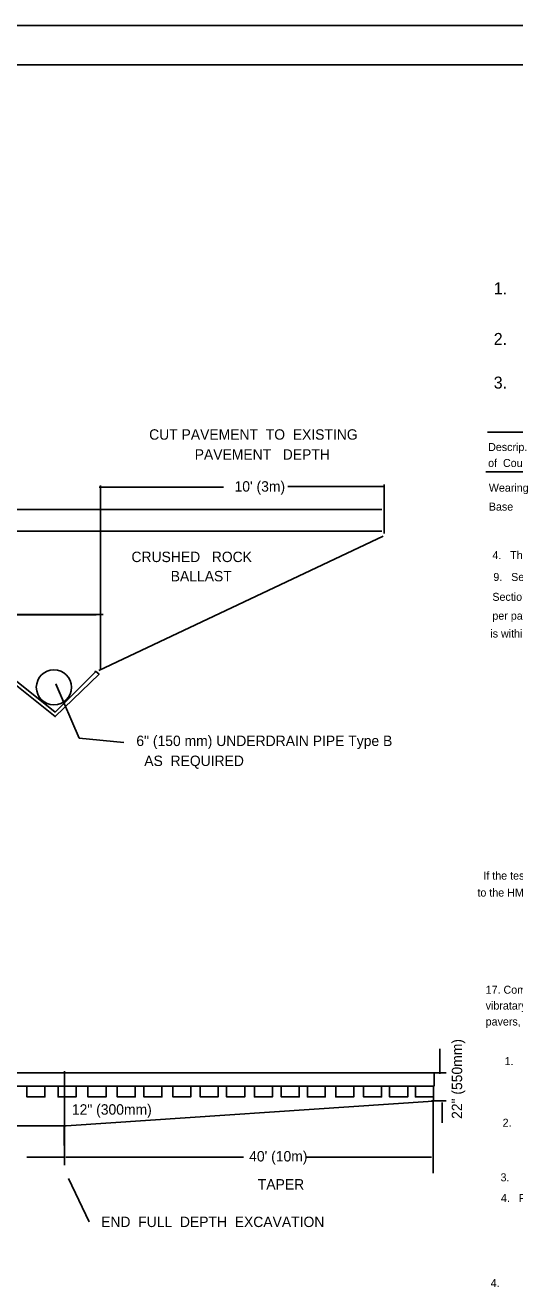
# Model space of a CAD drawing. Extents: x 1100953.69 to 1100956.55, y 386728.28 to 386730.11.
# Drawn here: x 1100955.371 to 1100955.772, y 386729.072 to 386730.11 of the extents above; entities that cross this region are included whole.
import ezdxf

# ---------------------------------------------------------------- set-up
doc = ezdxf.new("R2010")
doc.units = 0
for name, color, linetype in [('BORDER', 7, 'Continuous'), ('Level 1', 7, 'Continuous'), ('Level 33', 7, 'Continuous'), ('ORIG TOPO TEXT', 7, 'Continuous'), ('PLOT BOUNDARY', 7, 'Continuous'), ('ROADWAY TEXT', 7, 'Continuous')]:
    doc.layers.add(name, color=color, linetype=linetype)

msp = doc.modelspace()

# ---------------------------------------------------------------- linework, layer by layer
at = {"layer": 'BORDER'}
msp.add_line((1100956.4931, 386730.0776), (1100953.8264, 386730.0776), dxfattribs=at)
at = {"layer": 'Level 1'}
for p, q in [((1100955.4725, 386729.731), (1100955.5332, 386729.731)), ((1100955.6383, 386729.7317), (1100955.5861, 386729.7317)), ((1100955.4308, 386729.5806), (1100955.6643, 386729.6908)), ((1100953.8943, 386729.2506), (1100955.7055, 386729.2506)), ((1100955.7062, 386729.2506), (1100955.7062, 386729.2398)), ((1100955.4028, 386729.2451), (1100955.4028, 386729.175)), ((1100955.7052, 386729.2398), (1100955.7061, 386729.2398)), ((1100955.7053, 386729.2279), (1100955.7053, 386729.1684)), ((1100955.7055, 386729.2308), (1100955.7055, 386729.2275)), ((1100955.5496, 386729.1813), (1100955.4038, 386729.1813)), ((1100955.6008, 386729.1813), (1100955.704, 386729.1813))]:
    msp.add_line(p, q, dxfattribs=at)
for points in [[(1100955.4278, 386729.5793), (1100955.395, 386729.5465), (1100955.3578, 386729.5763), (1100955.3578, 386729.5763), (1100954.7625, 386729.591), (1100954.1599, 386729.574), (1100954.1361, 386729.5502), (1100954.1075, 386729.5787)], [(1100954.1044, 386729.5735), (1100954.1351, 386729.5442), (1100954.1598, 386729.5701), (1100954.7626, 386729.5873), (1100955.3554, 386729.5746), (1100955.3951, 386729.5429), (1100955.4313, 386729.5776), (1100955.4313, 386729.5776), (1100955.4313, 386729.5776), (1100955.4313, 386729.5776)], [(1100955.7055, 386729.2398), (1100953.8939, 386729.2398), (1100953.8939, 386729.2503)], [(1100953.8943, 386729.2398), (1100953.8943, 386729.2506), (1100953.8943, 386729.2506), (1100955.7062, 386729.2506), (1100955.7062, 386729.2398)], [(1100953.8943, 386729.2398), (1100953.8943, 386729.2398), (1100955.7055, 386729.2398)], [(1100955.3719, 386729.2398), (1100955.3719, 386729.2308), (1100955.3866, 386729.2308), (1100955.3866, 386729.2398)], [(1100955.3974, 386729.2398), (1100955.3974, 386729.2308), (1100955.4122, 386729.2308), (1100955.4122, 386729.2398)], [(1100955.422, 386729.2398), (1100955.422, 386729.2308), (1100955.4368, 386729.2308), (1100955.4368, 386729.2398)], [(1100955.446, 386729.2398), (1100955.446, 386729.2308), (1100955.4608, 386729.2308), (1100955.4608, 386729.2398)], [(1100955.4679, 386729.2398), (1100955.4679, 386729.2308), (1100955.4827, 386729.2308), (1100955.4827, 386729.2398)], [(1100955.4917, 386729.2398), (1100955.4917, 386729.2308), (1100955.5064, 386729.2308), (1100955.5064, 386729.2398)], [(1100955.5141, 386729.2398), (1100955.5141, 386729.2308), (1100955.5288, 386729.2308), (1100955.5288, 386729.2398)], [(1100955.5358, 386729.2398), (1100955.5358, 386729.2308), (1100955.5506, 386729.2308), (1100955.5506, 386729.2398)], [(1100955.5586, 386729.2398), (1100955.5586, 386729.2308), (1100955.5734, 386729.2308), (1100955.5734, 386729.2398)], [(1100955.5806, 386729.2398), (1100955.5806, 386729.2308), (1100955.5954, 386729.2308), (1100955.5954, 386729.2398)], [(1100955.6021, 386729.2398), (1100955.6021, 386729.2308), (1100955.6168, 386729.2308), (1100955.6168, 386729.2398)], [(1100955.6253, 386729.2398), (1100955.6253, 386729.2308), (1100955.6401, 386729.2308), (1100955.6401, 386729.2398)], [(1100955.6482, 386729.2398), (1100955.6482, 386729.2308), (1100955.6629, 386729.2308), (1100955.6629, 386729.2398)], [(1100955.6696, 386729.2398), (1100955.6696, 386729.2308), (1100955.6844, 386729.2308), (1100955.6844, 386729.2398)], [(1100955.6907, 386729.2398), (1100955.6907, 386729.2308), (1100955.7055, 386729.2308), (1100955.7055, 386729.2398)], [(1100954.1987, 386729.2072), (1100955.4041, 386729.2072), (1100955.7053, 386729.2275)]]:
    msp.add_lwpolyline(points, dxfattribs=at)
msp.add_circle((1100955.394, 386729.5669), 0.0144, dxfattribs=at)
at = {"layer": 'Level 33'}
for p, q in [((1100955.4323, 386729.7324), (1100955.4323, 386729.5818)), ((1100955.6651, 386729.7333), (1100955.6651, 386729.6931)), ((1100954.906, 386729.7126), (1100955.6632, 386729.7126)), ((1100955.6632, 386729.6949), (1100955.0388, 386729.6949)), ((1100954.8967, 386729.6263), (1100955.4288, 386729.6263)), ((1100954.9025, 386729.6266), (1100955.4346, 386729.6266))]:
    msp.add_line(p, q, dxfattribs=at)
msp.add_lwpolyline([(1100955.3958, 386729.569), (1100955.4149, 386729.5252), (1100955.4514, 386729.5215)], dxfattribs=at)
at = {"layer": 'ORIG TOPO TEXT'}
for p, q in [((1100955.7499, 386729.7762), (1100956.2809, 386729.7762)), ((1100955.7485, 386729.7436), (1100956.2795, 386729.7436)), ((1100955.4725, 386729.731), (1100955.4311, 386729.731)), ((1100955.6383, 386729.7317), (1100955.6648, 386729.7317)), ((1100955.4167, 386729.6267), (1100955.4301, 386729.6267)), ((1100955.4021, 386729.5545), (1100955.3957, 386729.5698)), ((1100955.7109, 386729.2704), (1100955.7109, 386729.2497)), ((1100955.4027, 386729.2519), (1100955.4027, 386729.2312)), ((1100955.7039, 386729.2507), (1100955.7159, 386729.2507)), ((1100955.7039, 386729.2276), (1100955.7159, 386729.2276)), ((1100955.7126, 386729.2096), (1100955.7126, 386729.2263)), ((1100955.4025, 386729.1909), (1100955.4025, 386729.2076)), ((1100955.3719, 386729.1814), (1100955.4019, 386729.1814)), ((1100955.423, 386729.1283), (1100955.4059, 386729.164))]:
    msp.add_line(p, q, dxfattribs=at)
msp.add_lwpolyline([(1100955.4313, 386729.5776), (1100955.4283, 386729.58), (1100955.4278, 386729.5793)], dxfattribs=at)
at = {"layer": 'PLOT BOUNDARY'}
msp.add_lwpolyline([(1100953.6916, 386728.2766), (1100956.5249, 386728.2766), (1100956.5249, 386730.1099), (1100953.6916, 386730.1099)], close=True, dxfattribs=at)

# ---------------------------------------------------------------- texts
at = {"layer": 'ORIG TOPO TEXT'}
for s, height, p in [('1.', 0.00984, (1100955.755, 386729.8892)), ('2.', 0.00984, (1100955.755, 386729.8477)), ('3.', 0.00984, (1100955.755, 386729.8119)), ('CUT PAVEMENT  TO  EXISTING', 0.008531, (1100955.4722, 386729.77)), ('Descrip.', 0.00656, (1100955.7504, 386729.7607)), ('PAVEMENT   DEPTH', 0.008531, (1100955.5096, 386729.7536)), ('of  Course', 0.00656, (1100955.7504, 386729.7476)), ("10' (3m)", 0.00853, (1100955.5423, 386729.7274)), ('Wearing', 0.00656, (1100955.751, 386729.7273)), ('Base', 0.00656, (1100955.751, 386729.7118)), ('CRUSHED   ROCK', 0.008531, (1100955.4577, 386729.6696)), ('CRUSHED   ROCK', 0.008531, (1100955.4577, 386729.6696)), ('4.   The design traffic level for the mix placed shall  be 0.3 to <3million ESALS', 0.006563, (1100955.7539, 386729.672)), ('BALLAST', 0.00853, (1100955.4899, 386729.6538)), ('9.   Section 106.6 Acceptance,(2) Method C-For hot mix asphalt designated as Method C in Special Provision ', 0.006563, (1100955.7547, 386729.6541)), ('Section 403 -Hot Mix Asphalt, one sample will be taken from the paver hopper or the truck body per 250 ton', 0.006563, (1100955.7539, 386729.6378)), ('per pay item. The mix will be tested for gradation and PGAB content. Disputes will not be allowed.  If the mix', 0.006563, (1100955.7539, 386729.6223)), ('is within tolerances listed in Table 9, Method C the Department will pay the contract unit price.', 0.006563, (1100955.7522, 386729.6077)), ('6" (150 mm) UNDERDRAIN PIPE Type B', 0.008531, (1100955.4617, 386729.5187)), ('AS  REQUIRED', 0.008531, (1100955.4682, 386729.5023)), ('If the test results for each 250 ton increment are outside these limits the following deductions(Table 9b) shall apply', 0.006563, (1100955.7465, 386729.4091)), (' to the HMA quantity represented by the test. A second consecutive failing test shall result in cessation of production', 0.006563, (1100955.7392, 386729.3952)), ('17. Compaction of the new Hot Mix Asphalt Pavement will be obtained using a minimal roller train consisting of a 3-5 ton', 0.006563, (1100955.7484, 386729.3155)), ('vibratary roller. An approved release agent is required to ensure the mixture does not adhere to hand tools,rollers, ', 0.006563, (1100955.7484, 386729.3025)), ('pavers, and truck bodies. The use of petroleum based fuel oils will not be permitted', 0.006563, (1100955.7484, 386729.2894)), ('1.   ', 0.00656, (1100955.7639, 386729.2569)), ('12" (300mm)', 0.008531, (1100955.4088, 386729.2163)), ('2.   ', 0.00656, (1100955.7623, 386729.2064)), ("40' (10m)", 0.00853, (1100955.5543, 386729.1779)), ('3.', 0.00656, (1100955.7606, 386729.1616)), ('TAPER', 0.00853, (1100955.5614, 386729.1549)), ('4.   Paved shoulders within the gage of the rail to point 24" (650mm) outside of the field side of each rail', 0.006563, (1100955.7609, 386729.1446)), ('END  FULL  DEPTH  EXCAVATION', 0.008531, (1100955.4328, 386729.1241))]:
    msp.add_text(s, height=height, dxfattribs=at).set_placement(p)
msp.add_text('22" (550mm)', height=0.008531, rotation=90, dxfattribs=at).set_placement((1100955.7291, 386729.2128))
at = {"layer": 'ROADWAY TEXT'}
msp.add_text('4.', height=0.00656, dxfattribs=at).set_placement((1100955.7525, 386729.0749))

doc.saveas('drawing.dxf')
